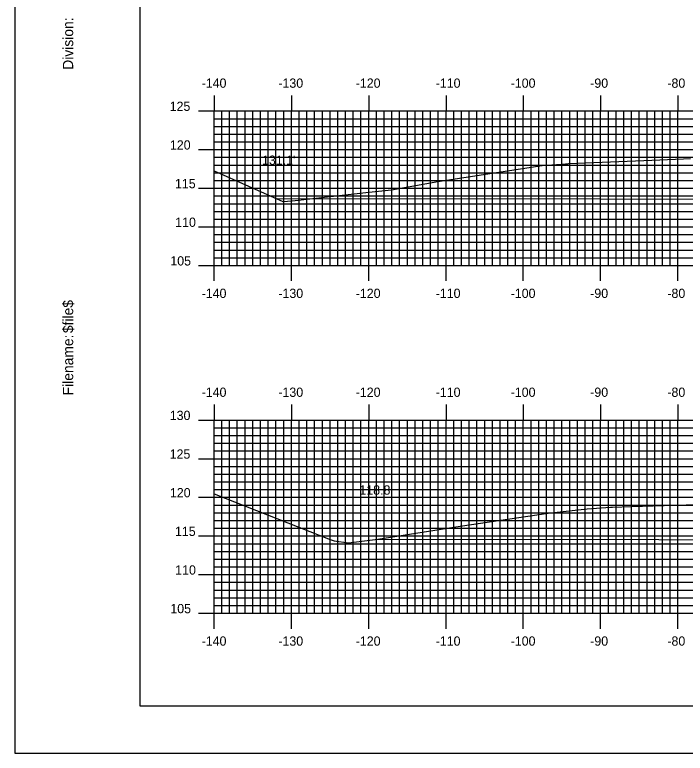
# Model space of a CAD drawing. Extents: x 855074 to 855418, y 366605 to 366825.
# Drawn here: x 855074.3 to 855161, y 366604.9 to 366700.5 of the extents above; entities that cross this region are included whole.
import ezdxf

# ---------------------------------------------------------------- set-up
doc = ezdxf.new("R2010")
doc.units = 0
for name, color, linetype in [('BORDER', 7, 'Continuous'), ('D_Roadway_Centerline', 7, 'Continuous'), ('D_Roadway_SubGrade', 7, 'Continuous'), ('D_Text_Standard', 7, 'Continuous'), ('H_V ANNOTATION', 7, 'Continuous'), ('MAJOR', 7, 'Continuous'), ('MINOR', 7, 'Continuous'), ('PLOT BOUNDARY', 7, 'Continuous'), ('S_Roadway_Centerline', 7, 'Continuous')]:
    doc.layers.add(name, color=color, linetype=linetype)

msp = doc.modelspace()

# ---------------------------------------------------------------- linework, layer by layer
at = {"layer": 'BORDER'}
msp.add_lwpolyline([(855090.469, 366611.055), (855410.469, 366611.055), (855410.469, 366821.055), (855090.469, 366821.055)], close=True, dxfattribs=at)
at = {"layer": 'D_Roadway_Centerline'}
msp.add_lwpolyline([(855121.285, 366632.643), (855193.895, 366632.57), (855193.895, 366632.57), (855194.457, 366632.711), (855197.169, 366633.389), (855197.171, 366633.389), (855201.825, 366634.553), (855208.07, 366636.114), (855208.073, 366636.114), (855214.211, 366636.36), (855216.07, 366636.434), (855228.067, 366636.674), (855228.069, 366636.674), (855240.065, 366636.914), (855240.069, 366636.914), (855240.071, 366636.914), (855244.592, 366637.004)], dxfattribs=at)
at = {"layer": 'D_Roadway_SubGrade'}
msp.add_lwpolyline([(855196.022, 366677.583), (855192.022, 366676.583), (855108.208, 366676.667)], dxfattribs=at)
at = {"layer": 'MAJOR'}
for p, q in [((855100.069, 366690.059), (855100.069, 366688.055)), ((855110.069, 366690.059), (855110.069, 366688.055)), ((855120.069, 366690.059), (855120.069, 366688.055)), ((855130.069, 366690.059), (855130.069, 366688.055)), ((855140.069, 366690.059), (855140.069, 366688.055)), ((855150.069, 366690.059), (855150.069, 366688.055)), ((855160.069, 366690.059), (855160.069, 366688.055)), ((855098.065, 366688.055), (855100.069, 366688.055)), ((855100.069, 366688.055), (855380.069, 366688.055)), ((855100.069, 366668.055), (855100.069, 366688.055)), ((855100.069, 366668.055), (855100.069, 366688.055)), ((855100.069, 366688.055), (855380.069, 366688.055)), ((855110.069, 366668.055), (855110.069, 366688.055)), ((855120.069, 366668.055), (855120.069, 366688.055)), ((855130.069, 366668.055), (855130.069, 366688.055)), ((855140.069, 366668.055), (855140.069, 366688.055)), ((855150.069, 366668.055), (855150.069, 366688.055)), ((855160.069, 366668.055), (855160.069, 366688.055)), ((855098.065, 366683.055), (855100.069, 366683.055)), ((855100.069, 366683.055), (855380.069, 366683.055)), ((855098.065, 366678.055), (855100.069, 366678.055)), ((855100.069, 366678.055), (855380.069, 366678.055)), ((855098.065, 366673.055), (855100.069, 366673.055)), ((855100.069, 366673.055), (855380.069, 366673.055)), ((855098.065, 366668.055), (855100.069, 366668.055)), ((855100.069, 366668.055), (855380.069, 366668.055)), ((855100.069, 366668.055), (855380.069, 366668.055)), ((855100.069, 366666.051), (855100.069, 366668.055)), ((855110.069, 366666.051), (855110.069, 366668.055)), ((855120.069, 366666.051), (855120.069, 366668.055)), ((855130.069, 366666.051), (855130.069, 366668.055)), ((855140.069, 366666.051), (855140.069, 366668.055)), ((855150.069, 366666.051), (855150.069, 366668.055)), ((855160.069, 366666.051), (855160.069, 366668.055)), ((855100.069, 366650.059), (855100.069, 366648.055)), ((855110.069, 366650.059), (855110.069, 366648.055)), ((855120.069, 366650.059), (855120.069, 366648.055)), ((855130.069, 366650.059), (855130.069, 366648.055)), ((855140.069, 366650.059), (855140.069, 366648.055)), ((855150.069, 366650.059), (855150.069, 366648.055)), ((855160.069, 366650.059), (855160.069, 366648.055)), ((855098.065, 366648.055), (855100.069, 366648.055)), ((855100.069, 366648.055), (855380.069, 366648.055)), ((855100.069, 366623.055), (855100.069, 366648.055)), ((855100.069, 366623.055), (855100.069, 366648.055)), ((855100.069, 366648.055), (855380.069, 366648.055)), ((855110.069, 366623.055), (855110.069, 366648.055)), ((855120.069, 366623.055), (855120.069, 366648.055)), ((855130.069, 366623.055), (855130.069, 366648.055)), ((855140.069, 366623.055), (855140.069, 366648.055)), ((855150.069, 366623.055), (855150.069, 366648.055)), ((855160.069, 366623.055), (855160.069, 366648.055)), ((855098.065, 366643.055), (855100.069, 366643.055)), ((855100.069, 366643.055), (855380.069, 366643.055)), ((855098.065, 366638.055), (855100.069, 366638.055)), ((855100.069, 366638.055), (855380.069, 366638.055)), ((855098.065, 366633.055), (855100.069, 366633.055)), ((855100.069, 366633.055), (855380.069, 366633.055)), ((855098.065, 366628.055), (855100.069, 366628.055)), ((855100.069, 366628.055), (855380.069, 366628.055)), ((855098.065, 366623.055), (855100.069, 366623.055)), ((855100.069, 366623.055), (855380.069, 366623.055)), ((855100.069, 366623.055), (855380.069, 366623.055)), ((855100.069, 366621.051), (855100.069, 366623.055)), ((855110.069, 366621.051), (855110.069, 366623.055)), ((855120.069, 366621.051), (855120.069, 366623.055)), ((855130.069, 366621.051), (855130.069, 366623.055)), ((855140.069, 366621.051), (855140.069, 366623.055)), ((855150.069, 366621.051), (855150.069, 366623.055)), ((855160.069, 366621.051), (855160.069, 366623.055))]:
    msp.add_line(p, q, dxfattribs=at)
at = {"layer": 'MINOR'}
for p, q in [((855101.069, 366668.055), (855101.069, 366688.055)), ((855102.069, 366668.055), (855102.069, 366688.055)), ((855103.069, 366668.055), (855103.069, 366688.055)), ((855104.069, 366668.055), (855104.069, 366688.055)), ((855105.069, 366668.055), (855105.069, 366688.055)), ((855106.069, 366668.055), (855106.069, 366688.055)), ((855107.069, 366668.055), (855107.069, 366688.055)), ((855108.069, 366668.055), (855108.069, 366688.055)), ((855109.069, 366668.055), (855109.069, 366688.055)), ((855111.069, 366668.055), (855111.069, 366688.055)), ((855112.069, 366668.055), (855112.069, 366688.055)), ((855113.069, 366668.055), (855113.069, 366688.055)), ((855114.069, 366668.055), (855114.069, 366688.055)), ((855115.069, 366668.055), (855115.069, 366688.055)), ((855116.069, 366668.055), (855116.069, 366688.055)), ((855117.069, 366668.055), (855117.069, 366688.055)), ((855118.069, 366668.055), (855118.069, 366688.055)), ((855119.069, 366668.055), (855119.069, 366688.055)), ((855121.069, 366668.055), (855121.069, 366688.055)), ((855122.069, 366668.055), (855122.069, 366688.055)), ((855123.069, 366668.055), (855123.069, 366688.055)), ((855124.069, 366668.055), (855124.069, 366688.055)), ((855125.069, 366668.055), (855125.069, 366688.055)), ((855126.069, 366668.055), (855126.069, 366688.055)), ((855127.069, 366668.055), (855127.069, 366688.055)), ((855128.069, 366668.055), (855128.069, 366688.055)), ((855129.069, 366668.055), (855129.069, 366688.055)), ((855131.069, 366668.055), (855131.069, 366688.055)), ((855132.069, 366668.055), (855132.069, 366688.055)), ((855133.069, 366668.055), (855133.069, 366688.055)), ((855134.069, 366668.055), (855134.069, 366688.055)), ((855135.069, 366668.055), (855135.069, 366688.055)), ((855136.069, 366668.055), (855136.069, 366688.055)), ((855137.069, 366668.055), (855137.069, 366688.055)), ((855138.069, 366668.055), (855138.069, 366688.055)), ((855139.069, 366668.055), (855139.069, 366688.055)), ((855141.069, 366668.055), (855141.069, 366688.055)), ((855142.069, 366668.055), (855142.069, 366688.055)), ((855143.069, 366668.055), (855143.069, 366688.055)), ((855144.069, 366668.055), (855144.069, 366688.055)), ((855145.069, 366668.055), (855145.069, 366688.055)), ((855146.069, 366668.055), (855146.069, 366688.055)), ((855147.069, 366668.055), (855147.069, 366688.055)), ((855148.069, 366668.055), (855148.069, 366688.055)), ((855149.069, 366668.055), (855149.069, 366688.055)), ((855151.069, 366668.055), (855151.069, 366688.055)), ((855152.069, 366668.055), (855152.069, 366688.055)), ((855153.069, 366668.055), (855153.069, 366688.055)), ((855154.069, 366668.055), (855154.069, 366688.055)), ((855155.069, 366668.055), (855155.069, 366688.055)), ((855156.069, 366668.055), (855156.069, 366688.055)), ((855157.069, 366668.055), (855157.069, 366688.055)), ((855158.069, 366668.055), (855158.069, 366688.055)), ((855159.069, 366668.055), (855159.069, 366688.055)), ((855100.069, 366687.055), (855380.069, 366687.055)), ((855100.069, 366687.055), (855102.073, 366687.055)), ((855100.069, 366686.055), (855380.069, 366686.055)), ((855100.069, 366686.055), (855102.073, 366686.055)), ((855100.069, 366685.055), (855380.069, 366685.055)), ((855100.069, 366685.055), (855102.073, 366685.055)), ((855100.069, 366684.055), (855380.069, 366684.055)), ((855100.069, 366684.055), (855102.073, 366684.055)), ((855100.069, 366682.055), (855380.069, 366682.055)), ((855100.069, 366682.055), (855102.073, 366682.055)), ((855100.069, 366681.055), (855380.069, 366681.055)), ((855100.069, 366681.055), (855102.073, 366681.055)), ((855100.069, 366680.055), (855380.069, 366680.055)), ((855100.069, 366680.055), (855102.073, 366680.055)), ((855100.069, 366679.055), (855380.069, 366679.055)), ((855100.069, 366679.055), (855102.073, 366679.055)), ((855100.069, 366677.055), (855380.069, 366677.055)), ((855100.069, 366677.055), (855102.073, 366677.055)), ((855100.069, 366676.055), (855380.069, 366676.055)), ((855100.069, 366676.055), (855102.073, 366676.055)), ((855100.069, 366675.055), (855380.069, 366675.055)), ((855100.069, 366675.055), (855102.073, 366675.055)), ((855100.069, 366674.055), (855380.069, 366674.055)), ((855100.069, 366674.055), (855102.073, 366674.055)), ((855100.069, 366672.055), (855380.069, 366672.055)), ((855100.069, 366672.055), (855102.073, 366672.055)), ((855100.069, 366671.055), (855380.069, 366671.055)), ((855100.069, 366671.055), (855102.073, 366671.055)), ((855100.069, 366670.055), (855380.069, 366670.055)), ((855100.069, 366670.055), (855102.073, 366670.055)), ((855100.069, 366669.055), (855380.069, 366669.055)), ((855100.069, 366669.055), (855102.073, 366669.055)), ((855101.069, 366623.055), (855101.069, 366648.055)), ((855102.069, 366623.055), (855102.069, 366648.055)), ((855103.069, 366623.055), (855103.069, 366648.055)), ((855104.069, 366623.055), (855104.069, 366648.055)), ((855105.069, 366623.055), (855105.069, 366648.055)), ((855106.069, 366623.055), (855106.069, 366648.055)), ((855107.069, 366623.055), (855107.069, 366648.055)), ((855108.069, 366623.055), (855108.069, 366648.055)), ((855109.069, 366623.055), (855109.069, 366648.055)), ((855111.069, 366623.055), (855111.069, 366648.055)), ((855112.069, 366623.055), (855112.069, 366648.055)), ((855113.069, 366623.055), (855113.069, 366648.055)), ((855114.069, 366623.055), (855114.069, 366648.055)), ((855115.069, 366623.055), (855115.069, 366648.055)), ((855116.069, 366623.055), (855116.069, 366648.055)), ((855117.069, 366623.055), (855117.069, 366648.055)), ((855118.069, 366623.055), (855118.069, 366648.055)), ((855119.069, 366623.055), (855119.069, 366648.055)), ((855121.069, 366623.055), (855121.069, 366648.055)), ((855122.069, 366623.055), (855122.069, 366648.055)), ((855123.069, 366623.055), (855123.069, 366648.055)), ((855124.069, 366623.055), (855124.069, 366648.055)), ((855125.069, 366623.055), (855125.069, 366648.055)), ((855126.069, 366623.055), (855126.069, 366648.055)), ((855127.069, 366623.055), (855127.069, 366648.055)), ((855128.069, 366623.055), (855128.069, 366648.055)), ((855129.069, 366623.055), (855129.069, 366648.055)), ((855131.069, 366623.055), (855131.069, 366648.055)), ((855132.069, 366623.055), (855132.069, 366648.055)), ((855133.069, 366623.055), (855133.069, 366648.055)), ((855134.069, 366623.055), (855134.069, 366648.055)), ((855135.069, 366623.055), (855135.069, 366648.055)), ((855136.069, 366623.055), (855136.069, 366648.055)), ((855137.069, 366623.055), (855137.069, 366648.055)), ((855138.069, 366623.055), (855138.069, 366648.055)), ((855139.069, 366623.055), (855139.069, 366648.055)), ((855141.069, 366623.055), (855141.069, 366648.055)), ((855142.069, 366623.055), (855142.069, 366648.055)), ((855143.069, 366623.055), (855143.069, 366648.055)), ((855144.069, 366623.055), (855144.069, 366648.055)), ((855145.069, 366623.055), (855145.069, 366648.055)), ((855146.069, 366623.055), (855146.069, 366648.055)), ((855147.069, 366623.055), (855147.069, 366648.055)), ((855148.069, 366623.055), (855148.069, 366648.055)), ((855149.069, 366623.055), (855149.069, 366648.055)), ((855151.069, 366623.055), (855151.069, 366648.055)), ((855152.069, 366623.055), (855152.069, 366648.055)), ((855153.069, 366623.055), (855153.069, 366648.055)), ((855154.069, 366623.055), (855154.069, 366648.055)), ((855155.069, 366623.055), (855155.069, 366648.055)), ((855156.069, 366623.055), (855156.069, 366648.055)), ((855157.069, 366623.055), (855157.069, 366648.055)), ((855158.069, 366623.055), (855158.069, 366648.055)), ((855159.069, 366623.055), (855159.069, 366648.055)), ((855100.069, 366647.055), (855380.069, 366647.055)), ((855100.069, 366647.055), (855102.073, 366647.055)), ((855100.069, 366646.055), (855380.069, 366646.055)), ((855100.069, 366646.055), (855102.073, 366646.055)), ((855100.069, 366645.055), (855380.069, 366645.055)), ((855100.069, 366645.055), (855102.073, 366645.055)), ((855100.069, 366644.055), (855380.069, 366644.055)), ((855100.069, 366644.055), (855102.073, 366644.055)), ((855100.069, 366642.055), (855380.069, 366642.055)), ((855100.069, 366642.055), (855102.073, 366642.055)), ((855100.069, 366641.055), (855380.069, 366641.055)), ((855100.069, 366641.055), (855102.073, 366641.055)), ((855100.069, 366640.055), (855380.069, 366640.055)), ((855100.069, 366640.055), (855102.073, 366640.055)), ((855100.069, 366639.055), (855380.069, 366639.055)), ((855100.069, 366639.055), (855102.073, 366639.055)), ((855100.069, 366637.055), (855380.069, 366637.055)), ((855100.069, 366637.055), (855102.073, 366637.055)), ((855100.069, 366636.055), (855380.069, 366636.055)), ((855100.069, 366636.055), (855102.073, 366636.055)), ((855100.069, 366635.055), (855380.069, 366635.055)), ((855100.069, 366635.055), (855102.073, 366635.055)), ((855100.069, 366634.055), (855380.069, 366634.055)), ((855100.069, 366634.055), (855102.073, 366634.055)), ((855100.069, 366632.055), (855380.069, 366632.055)), ((855100.069, 366632.055), (855102.073, 366632.055)), ((855100.069, 366631.055), (855380.069, 366631.055)), ((855100.069, 366631.055), (855102.073, 366631.055)), ((855100.069, 366630.055), (855380.069, 366630.055)), ((855100.069, 366630.055), (855102.073, 366630.055)), ((855100.069, 366629.055), (855380.069, 366629.055)), ((855100.069, 366629.055), (855102.073, 366629.055)), ((855100.069, 366627.055), (855380.069, 366627.055)), ((855100.069, 366627.055), (855102.073, 366627.055)), ((855100.069, 366626.055), (855380.069, 366626.055)), ((855100.069, 366626.055), (855102.073, 366626.055)), ((855100.069, 366625.055), (855380.069, 366625.055)), ((855100.069, 366625.055), (855102.073, 366625.055)), ((855100.069, 366624.055), (855380.069, 366624.055)), ((855100.069, 366624.055), (855102.073, 366624.055))]:
    msp.add_line(p, q, dxfattribs=at)
at = {"layer": 'PLOT BOUNDARY'}
msp.add_lwpolyline([(855074.283, 366604.937), (855414.283, 366604.937), (855414.283, 366824.937), (855074.283, 366824.937)], close=True, dxfattribs=at)
at = {"layer": 'S_Roadway_Centerline'}
for points in [[(855100.069, 366680.31), (855108.943, 366676.338), (855110.151, 366676.428), (855120.067, 366677.563), (855123.004, 366677.846), (855129.003, 366678.907), (855142.516, 366680.975), (855144.34, 366681.123), (855145.51, 366681.201), (855145.719, 366681.224), (855145.829, 366681.227), (855145.974, 366681.238), (855155.65, 366681.656), (855160.783, 366681.879), (855161.681, 366681.921)], [(855100.069, 366638.485), (855115.085, 366632.607), (855115.592, 366632.435), (855117.47, 366632.166), (855121.259, 366632.639), (855131.882, 366634.338), (855143.28, 366636.014), (855148.328, 366636.547), (855151.36, 366636.779), (855151.598, 366636.79), (855154.063, 366636.86), (855169.573, 366637.331)]]:
    msp.add_lwpolyline(points, dxfattribs=at)

# ---------------------------------------------------------------- texts
at = {"layer": 'BORDER'}
for s, p in [('Division:', (855081.839, 366693.387)), ('$file$', (855081.839, 366659.306)), ('Filename:', (855081.839, 366651.252))]:
    msp.add_text(s, height=1.3392, rotation=90, dxfattribs=at).set_placement(p)
at = {"layer": 'D_Text_Standard'}
for s, p in [("131.1'", (855106.269, 366681.087)), ("118.8'", (855118.861, 366638.402))]:
    msp.add_text(s, height=1.2, dxfattribs=at).set_placement(p)
at = {"layer": 'H_V ANNOTATION'}
for s, p in [('-140', (855098.453, 366691.055)), ('-130', (855108.378, 366691.055)), ('-120', (855118.389, 366691.055)), ('-110', (855128.732, 366691.055)), ('-100', (855138.432, 366691.055)), ('-90', (855148.721, 366691.055)), ('-80', (855158.699, 366691.055)), ('125', (855094.318, 366688.055)), ('120', (855094.35, 366683.055)), ('115', (855095.004, 366678.055)), ('110', (855095.036, 366673.055)), ('105', (855094.404, 366668.055)), ('-140', (855098.453, 366663.855)), ('-130', (855108.378, 366663.855)), ('-120', (855118.389, 366663.855)), ('-110', (855128.732, 366663.855)), ('-100', (855138.432, 366663.855)), ('-90', (855148.721, 366663.855)), ('-80', (855158.699, 366663.855)), ('-140', (855098.453, 366651.055)), ('-130', (855108.378, 366651.055)), ('-120', (855118.389, 366651.055)), ('-110', (855128.732, 366651.055)), ('-100', (855138.432, 366651.055)), ('-90', (855148.721, 366651.055)), ('-80', (855158.699, 366651.055)), ('130', (855094.329, 366648.055)), ('125', (855094.318, 366643.055)), ('120', (855094.35, 366638.055)), ('115', (855095.004, 366633.055)), ('110', (855095.036, 366628.055)), ('105', (855094.404, 366623.055)), ('-140', (855098.453, 366618.855)), ('-130', (855108.378, 366618.855)), ('-120', (855118.389, 366618.855)), ('-110', (855128.732, 366618.855)), ('-100', (855138.432, 366618.855)), ('-90', (855148.721, 366618.855)), ('-80', (855158.699, 366618.855))]:
    msp.add_text(s, height=1.2, dxfattribs=at).set_placement(p)
at = {"layer": 'MAJOR'}
for p in [(855100.06, 366668.055), (855100.06, 366623.055)]:
    msp.add_text('-', height=0.012, dxfattribs=at).set_placement(p)

doc.saveas('drawing.dxf')
